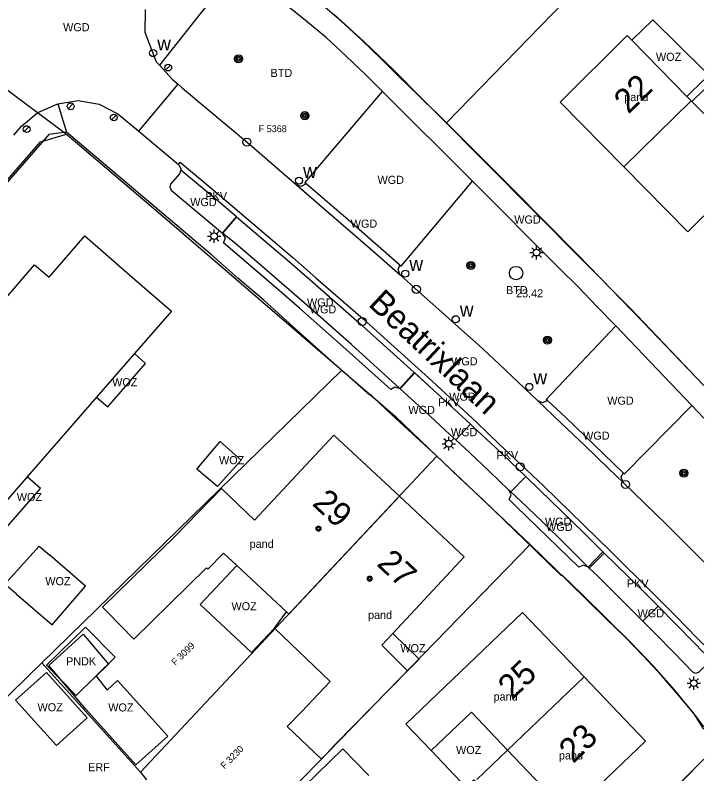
# Model space of a CAD drawing. Extents: x 198240 to 198429, y 356553 to 356721.
# Drawn here: x 198378.2 to 198429.3, y 356582.9 to 356639.1 of the extents above; entities that cross this region are included whole.
import ezdxf

# ---------------------------------------------------------------- set-up
doc = ezdxf.new("R2010")
doc.units = 0
for name, color, linetype in [('(presentatie) Code PNDK (symbool) (zonder attributen) niet in de presentatietabel', 7, 'Continuous'), ('Afsluitpaal', 7, 'Continuous'), ('begroeid terreindeel kenmerkpunt', 7, 'Continuous'), ('bijgebouw', 7, 'Continuous'), ('BOOM', 7, 'Continuous'), ('grens individueel parkeervak', 7, 'Continuous'), ('Grens maaiveld', 7, 'Continuous'), ('grens WOZ object', 7, 'Continuous'), ('hoofdgebouw', 7, 'Continuous'), ('Hoogtepunt', 7, 'Continuous'), ('huisnummerreeks BGT', 7, 'Continuous'), ('identificerend kenmerkpunt pand', 7, 'Continuous'), ('identificerend kenmerkpunt parkeervak', 7, 'Continuous'), ('identificerend kenmerkpunt WOZ object', 7, 'Continuous'), ('Inspectieput_rioolput', 7, 'Continuous'), ('kant verharding', 7, 'Continuous'), ('kolk', 7, 'Continuous'), ('LICHTMAST', 7, 'Continuous'), ('onbegroeid terreindeel kenmerkpunt', 7, 'Continuous'), ('openbare ruimte label tekst', 7, 'Continuous'), ('Perceelnummer', 7, 'Continuous'), ('perceelsgrens_definitief', 7, 'Continuous'), ('tussenmuur', 7, 'Continuous'), ('vlakafsluiter', 7, 'Continuous'), ('waterleidingput', 7, 'Continuous'), ('wegdeel kenmerkpunt', 7, 'Continuous'), ('weginrichtingselement lijn', 7, 'Continuous'), ('WOZ object als punt', 7, 'Continuous')]:
    doc.layers.add(name, color=color, linetype=linetype)

msp = doc.modelspace()

# ---------------------------------------------------------------- linework, layer by layer
at = {"layer": 'Afsluitpaal'}
for p, q in [((198389.752, 356635.373), (198389.402, 356635.016)), ((198382.523, 356632.501), (198382.173, 356632.144)), ((198385.717, 356631.672), (198385.367, 356631.315)), ((198379.266, 356630.817), (198378.916, 356630.46))]:
    msp.add_line(p, q, dxfattribs=at)
for centre in [(198389.579, 356635.193), (198382.35, 356632.321), (198385.544, 356631.492), (198379.093, 356630.637)]:
    msp.add_circle(centre, 0.25, dxfattribs=at)
at = {"layer": 'bijgebouw'}
msp.add_lwpolyline([(198404.433, 356582.738), (198402.513, 356584.711), (198393.844, 356576.278)], dxfattribs=at)
at = {"layer": 'BOOM'}
for centre, radius in [((198394.789, 356635.842), 0.3), ((198394.789, 356635.842), 0.2), ((198394.789, 356635.842), 0.1), ((198399.701, 356631.63), 0.3), ((198399.701, 356631.63), 0.2), ((198399.701, 356631.63), 0.1), ((198412, 356620.53), 0.3), ((198412, 356620.53), 0.2), ((198412, 356620.53), 0.1), ((198417.666, 356614.998), 0.3), ((198417.666, 356614.998), 0.2), ((198417.666, 356614.998), 0.1), ((198427.773, 356605.142), 0.3), ((198427.773, 356605.142), 0.2), ((198427.773, 356605.142), 0.1)]:
    msp.add_circle(centre, radius, dxfattribs=at)
at = {"layer": 'grens individueel parkeervak'}
for p, q in [((198393.611, 356622.929), (198394.644, 356624.13)), ((198406.736, 356611.407), (198407.804, 356612.596)), ((198407.804, 356612.596), (198408.885, 356611.623)), ((198408.885, 356611.623), (198411.957, 356608.785)), ((198411.957, 356608.785), (198410.875, 356607.614)), ((198416.055, 356604.889), (198414.957, 356603.76)), ((198420.762, 356598.101), (198421.877, 356599.222)), ((198425.862, 356595.279), (198424.743, 356594.175))]:
    msp.add_line(p, q, dxfattribs=at)
at = {"layer": 'Grens maaiveld'}
for p, q in [((198387.401, 356630.486), (198390.303, 356633.969)), ((198412.108, 356626.778), (198405.457, 356633.424)), ((198394.647, 356624.128), (198393.611, 356622.929)), ((198394.644, 356624.13), (198394.647, 356624.128)), ((198428.353, 356610.158), (198422.727, 356616.058)), ((198407.835, 356612.568), (198406.758, 356611.387)), ((198407.804, 356612.596), (198407.835, 356612.568)), ((198407.835, 356612.568), (198408.885, 356611.623)), ((198421.782, 356599.316), (198420.673, 356598.187)), ((198421.782, 356599.316), (198421.877, 356599.222))]:
    msp.add_line(p, q, dxfattribs=at)
for points in [[(198390.351, 356628.02), (198390.474, 356628.186), (198393.38, 356625.746), (198398.817, 356621.126), (198400.515, 356619.62), (198404.027, 356616.565), (198409.139, 356611.949), (198412.449, 356608.888), (198414.07, 356607.327), (198415.701, 356605.794), (198417.373, 356604.2), (198422.346, 356599.356), (198425.506, 356596.239), (198427.177, 356594.549), (198428.749, 356592.925), (198429.251, 356592.414)], [(198394.647, 356624.128), (198398.552, 356620.797), (198400.287, 356619.294), (198403.74, 356616.251), (198407.804, 356612.596)], [(198416.055, 356604.889), (198417.102, 356603.887), (198420.322, 356600.761), (198421.782, 356599.316)], [(198382.763, 356588.673), (198385.648, 356591.501), (198383.456, 356593.736), (198380.572, 356590.908), (198382.763, 356588.673)]]:
    msp.add_lwpolyline(points, dxfattribs=at)
at = {"layer": 'grens WOZ object'}
for p, q in [((198428.372, 356632.684), (198429.251, 356633.549)), ((198391.948, 356595.404), (198394.663, 356598.297)), ((198395.738, 356591.846), (198391.948, 356595.404)), ((198397.445, 356593.664), (198395.738, 356591.846)), ((198412.437, 356582.444), (198414.721, 356584.63))]:
    msp.add_line(p, q, dxfattribs=at)
for points in [[(198423.912, 356637.214), (198425.477, 356638.743), (198429.251, 356635.003)], [(198429.251, 356634.286), (198428.004, 356633.058)], [(198384.269, 356610.774), (198385.099, 356610.052), (198387.904, 356613.278), (198387.074, 356614)], [(198391.701, 356605.434), (198393.43, 356607.5), (198394.985, 356606.117), (198393.222, 356604.147), (198391.701, 356605.434)], [(198376.42, 356601.748), (198377.399, 356600.897), (198380.113, 356604.018), (198379.134, 356604.869)], [(198378.332, 356596.184), (198377.486, 356596.927), (198380.014, 356599.745), (198380.819, 356599.057)], [(198378.332, 356596.184), (198380.974, 356593.898), (198383.461, 356596.771), (198380.819, 356599.057)], [(198383.475, 356587.665), (198380.724, 356590.901), (198383.272, 356593.219), (198385.145, 356590.982), (198384.231, 356590.1), (198385.044, 356589.073)], [(198407.305, 356590.49), (198408.161, 356591.371), (198406.214, 356593.274)], [(198380.563, 356590.378), (198383.579, 356587.014), (198381.293, 356584.965), (198378.277, 356588.329), (198380.563, 356590.378)], [(198383.475, 356587.665), (198387.187, 356583.535), (198389.545, 356585.651), (198385.833, 356589.781), (198385.044, 356589.073)], [(198409.054, 356584.582), (198411.65, 356581.864), (198412.216, 356582.419), (198412.308, 356582.321)]]:
    msp.add_lwpolyline(points, dxfattribs=at)
at = {"layer": 'hoofdgebouw'}
for p, q in [((198423.912, 356637.214), (198428.004, 356633.058)), ((198428.004, 356633.058), (198428.318, 356632.739)), ((198428.372, 356632.684), (198428.318, 356632.739)), ((198428.372, 356632.684), (198429.251, 356631.791)), ((198387.106, 356619.502), (198389.812, 356617.148)), ((198389.812, 356617.148), (198387.074, 356614)), ((198387.074, 356614), (198384.269, 356610.774)), ((198384.269, 356610.774), (198379.134, 356604.869)), ((198379.134, 356604.869), (198376.42, 356601.748)), ((198393.684, 356599.212), (198394.663, 356598.297)), ((198394.663, 356598.297), (198398.338, 356594.861)), ((198385.074, 356594.841), (198387.025, 356592.851)), ((198397.445, 356593.664), (198398.338, 356594.861)), ((198405.392, 356592.395), (198406.214, 356593.274)), ((198407.305, 356590.49), (198405.392, 356592.395)), ((198401.981, 356585.072), (198407.305, 356590.49))]:
    msp.add_line(p, q, dxfattribs=at)
for points in [[(198423.328, 356627.83), (198418.602, 356632.63), (198423.566, 356637.565), (198423.912, 356637.214)], [(198423.328, 356627.83), (198428.055, 356623.028), (198429.251, 356624.217)], [(198360.274, 356583.182), (198357.56, 356580.061), (198351.153, 356585.634), (198353.818, 356588.702), (198352.758, 356589.611), (198356.269, 356593.637), (198357.324, 356592.737), (198361.192, 356597.186), (198360.148, 356598.119), (198363.635, 356602.123), (198364.703, 356601.223), (198369.86, 356607.147), (198368.781, 356608.057), (198372.281, 356612.093), (198373.369, 356611.185), (198377.239, 356615.604), (198376.168, 356616.531), (198379.668, 356620.576), (198380.75, 356619.653), (198383.405, 356622.721), (198387.106, 356619.502)], [(198406.698, 356603.432), (198401.85, 356607.965), (198395.961, 356601.666)], [(198395.961, 356601.666), (198393.536, 356604.004), (198390.102, 356600.479), (198384.72, 356595.202), (198385.074, 356594.841)], [(198406.214, 356593.274), (198411.508, 356598.935), (198406.698, 356603.432)], [(198387.025, 356592.851), (198392.407, 356598.128), (198392.518, 356598.036), (198393.684, 356599.212)], [(198420.379, 356590.045), (198415.818, 356594.814), (198407.174, 356586.548), (198409.054, 356584.582)], [(198399.458, 356587.46), (198401.569, 356589.712), (198397.445, 356593.664)], [(198414.721, 356584.63), (198419.264, 356579.863), (198424.933, 356585.283), (198420.379, 356590.045)], [(198401.981, 356585.072), (198400.944, 356583.951), (198398.386, 356586.376), (198399.458, 356587.46)], [(198414.721, 356584.63), (198412.038, 356587.436), (198409.054, 356584.582)]]:
    msp.add_lwpolyline(points, dxfattribs=at)
at = {"layer": 'Inspectieput_rioolput'}
msp.add_circle((198415.345, 356619.967), 0.5, dxfattribs=at)
at = {"layer": 'kant verharding'}
for p, q in [((198387.401, 356630.486), (198390.351, 356628.02)), ((198406.758, 356611.387), (198406.736, 356611.407)), ((198414.957, 356603.76), (198414.818, 356603.89)), ((198420.762, 356598.101), (198420.673, 356598.187))]:
    msp.add_line(p, q, dxfattribs=at)
for points in [[(198429.251, 356611.63), (198423.819, 356617.345), (198409.544, 356631.708), (198408.091, 356633.148), (198406.605, 356634.587), (198405.359, 356635.839), (198403.884, 356637.248), (198402.388, 356638.638), (198400.833, 356639.97), (198393.74, 356645.683)], [(198405.457, 356633.424), (198404.207, 356634.656), (198402.756, 356636.046), (198401.298, 356637.391), (198399.756, 356638.679), (198394.727, 356642.73), (198388.921, 356635.368)], [(198388.921, 356635.368), (198388.706, 356635.6), (198387.879, 356637.792), (198387.884, 356639.508)], [(198388.921, 356635.368), (198389.879, 356634.336), (198390.303, 356633.969)], [(198390.303, 356633.969), (198390.646, 356633.671), (198395.594, 356629.511), (198399.076, 356626.51)], [(198399.794, 356626.571), (198399.707, 356626.646), (198405.457, 356633.424)], [(198378.133, 356630.181), (198378.722, 356630.856), (198379.929, 356631.864), (198381.394, 356632.501)], [(198381.394, 356632.501), (198382.909, 356632.765), (198384.458, 356632.488), (198385.857, 356631.776), (198387.401, 356630.486)], [(198382.054, 356630.413), (198380.73, 356630.231), (198344.191, 356588.273)], [(198429.251, 356586.163), (198428.533, 356587.306), (198427.059, 356589.105), (198425.554, 356590.824), (198423.841, 356592.587), (198422.054, 356594.368), (198420.263, 356596.131), (198418.74, 356597.61), (198418.684, 356597.56), (198416.787, 356599.424), (198412.901, 356603.163), (198411.158, 356604.8), (198409.368, 356606.497), (198407.657, 356608.089), (198405.801, 356609.79), (198404.573, 356610.98), (198404.508, 356610.918), (198402.536, 356612.682), (198400.516, 356614.473), (198398.571, 356616.223), (198396.659, 356617.972), (198394.731, 356619.585), (198392.786, 356621.33), (198382.054, 356630.413)], [(198390.351, 356628.02), (198390.534, 356627.659), (198390.507, 356627.59)], [(198390.507, 356627.59), (198390.403, 356627.322), (198389.759, 356626.559), (198389.689, 356626.348), (198389.807, 356626.113), (198393.611, 356622.929)], [(198394.644, 356624.13), (198393.131, 356625.407), (198390.507, 356627.59)], [(198406.743, 356620.544), (198406.825, 356620.476), (198412.108, 356626.778)], [(198422.727, 356616.058), (198421.324, 356617.489), (198419.957, 356618.916), (198418.514, 356620.35), (198412.108, 356626.778)], [(198399.794, 356626.571), (198399.424, 356626.383), (198399.076, 356626.51)], [(198399.076, 356626.51), (198400.741, 356625.063), (198404.376, 356621.927), (198406.764, 356619.84)], [(198406.743, 356620.544), (198404.729, 356622.319), (198402.899, 356623.906), (198399.794, 356626.571)], [(198406.758, 356611.387), (198406.365, 356611.514), (198406.061, 356611.341), (198402.761, 356614.308), (198399.298, 356617.361), (198397.596, 356618.846), (198393.68, 356622.21), (198393.81, 356622.554), (198393.611, 356622.929)], [(198406.736, 356611.407), (198403.153, 356614.683), (198399.647, 356617.764), (198396.145, 356620.789), (198394.601, 356622.108), (198393.611, 356622.929)], [(198406.764, 356619.84), (198406.601, 356620.23), (198406.743, 356620.544)], [(198406.764, 356619.84), (198408.114, 356618.611), (198409.623, 356617.277), (198411.103, 356615.939), (198412.586, 356614.617), (198414.071, 356613.249), (198416.967, 356610.501)], [(198417.676, 356610.523), (198417.585, 356610.6), (198422.727, 356616.058)], [(198410.875, 356607.614), (198410.442, 356608.018), (198408.98, 356609.362), (198406.758, 356611.387)], [(198417.676, 356610.523), (198417.312, 356610.35), (198416.967, 356610.501)], [(198416.967, 356610.501), (198418.668, 356608.867), (198420.467, 356607.157), (198422.176, 356605.508), (198423.279, 356604.461)], [(198423.272, 356605.163), (198422.544, 356605.881), (198419.02, 356609.266), (198417.676, 356610.523)], [(198423.272, 356605.163), (198423.364, 356605.094), (198428.353, 356610.158)], [(198428.353, 356610.158), (198429.251, 356609.211)], [(198416.055, 356604.889), (198413.83, 356607.034), (198412.177, 356608.581), (198411.957, 356608.785)], [(198414.818, 356603.89), (198413.368, 356605.259), (198411.917, 356606.643), (198410.875, 356607.614)], [(198423.279, 356604.461), (198423.13, 356604.836), (198423.272, 356605.163)], [(198423.279, 356604.461), (198426.468, 356601.352), (198429.251, 356598.568)], [(198420.673, 356598.187), (198420.308, 356598.332), (198419.984, 356598.175), (198416.909, 356601.174), (198415.317, 356602.709), (198414.834, 356603.184), (198414.984, 356603.525), (198414.818, 356603.89)], [(198420.673, 356598.187), (198418.992, 356599.876), (198417.293, 356601.53), (198415.671, 356603.088), (198414.957, 356603.76)], [(198425.862, 356595.279), (198425.221, 356595.929), (198423.654, 356597.485), (198421.877, 356599.222)], [(198424.743, 356594.175), (198424.243, 356594.68), (198422.818, 356596.095), (198421.388, 356597.499), (198420.762, 356598.101)], [(198429.251, 356591.826), (198428.484, 356592.618), (198425.862, 356595.279)], [(198429.251, 356590.76), (198428.855, 356590.38), (198428.626, 356590.299), (198428.426, 356590.389), (198427.052, 356591.822), (198425.646, 356593.263), (198424.743, 356594.175)], [(198398.992, 356553.702), (198424.254, 356578.89), (198429.251, 356583.945)]]:
    msp.add_lwpolyline(points, dxfattribs=at)
at = {"layer": 'kolk'}
for centre in [(198395.405, 356629.673), (198407.955, 356618.764), (198403.943, 356616.375), (198415.642, 356605.618), (198423.454, 356604.309)]:
    msp.add_circle(centre, 0.3, dxfattribs=at)
at = {"layer": 'LICHTMAST'}
for p, q in [((198392.482, 356622.698), (198392.732, 356622.698)), ((198392.805, 356622.875), (198392.628, 356623.052)), ((198392.982, 356622.948), (198392.982, 356623.198)), ((198393.159, 356622.875), (198393.336, 356623.052)), ((198393.232, 356622.698), (198393.482, 356622.698)), ((198392.628, 356622.344), (198392.805, 356622.521)), ((198392.982, 356622.198), (198392.982, 356622.448)), ((198393.336, 356622.344), (198393.159, 356622.521)), ((198416.685, 356621.662), (198416.508, 356621.839)), ((198416.862, 356621.735), (198416.862, 356621.985)), ((198417.039, 356621.662), (198417.216, 356621.839)), ((198416.362, 356621.485), (198416.612, 356621.485)), ((198416.508, 356621.131), (198416.685, 356621.308)), ((198416.862, 356620.985), (198416.862, 356621.235)), ((198417.216, 356621.131), (198417.039, 356621.308)), ((198417.112, 356621.485), (198417.362, 356621.485)), ((198410.181, 356607.504), (198410.004, 356607.681)), ((198410.358, 356607.577), (198410.358, 356607.827)), ((198410.535, 356607.504), (198410.712, 356607.681)), ((198409.858, 356607.327), (198410.108, 356607.327)), ((198410.004, 356606.973), (198410.181, 356607.15)), ((198410.358, 356606.827), (198410.358, 356607.077)), ((198410.712, 356606.973), (198410.535, 356607.15)), ((198410.608, 356607.327), (198410.858, 356607.327)), ((198428.514, 356589.829), (198428.514, 356590.079)), ((198428.014, 356589.579), (198428.264, 356589.579)), ((198428.337, 356589.756), (198428.16, 356589.933)), ((198428.691, 356589.756), (198428.868, 356589.933)), ((198428.764, 356589.579), (198429.014, 356589.579)), ((198428.16, 356589.225), (198428.337, 356589.402)), ((198428.514, 356589.079), (198428.514, 356589.329)), ((198428.868, 356589.225), (198428.691, 356589.402))]:
    msp.add_line(p, q, dxfattribs=at)
for centre in [(198392.982, 356622.698), (198416.862, 356621.485), (198410.358, 356607.327), (198428.514, 356589.579)]:
    msp.add_circle(centre, 0.25, dxfattribs=at)
at = {"layer": 'perceelsgrens_definitief'}
for points in [[(198410.2, 356631.088), (198424.066, 356645.393)], [(198408.397, 356632.877), (198406.267, 356635.018), (198404.086, 356637.108), (198401.857, 356639.146)], [(198372.192, 356637.612), (198382.048, 356630.256)], [(198410.2, 356631.088), (198408.397, 356632.877)], [(198429.251, 356611.64), (198424.754, 356616.33), (198419.937, 356621.283), (198415.086, 356626.203), (198410.2, 356631.088)], [(198344.27, 356586.164), (198344.308, 356588.473), (198380.117, 356629.684), (198382.048, 356630.256)], [(198382.048, 356630.256), (198389.679, 356623.767), (198402.434, 356612.775)], [(198402.434, 356612.775), (198380.205, 356591.088)], [(198402.434, 356612.775), (198406.392, 356609.366), (198409.477, 356606.392)], [(198387.513, 356582.994), (198409.477, 356606.392)], [(198409.477, 356606.392), (198416.379, 356599.858)], [(198393.504, 356576.321), (198416.379, 356599.858)], [(198422.026, 356594.351), (198419.212, 356597.114), (198416.379, 356599.858)], [(198428.623, 356587.179), (198427.386, 356588.687), (198426.107, 356590.16), (198424.787, 356591.595), (198423.426, 356592.993), (198422.026, 356594.351)], [(198358.164, 356569.531), (198380.205, 356591.088)], [(198380.205, 356591.088), (198387.513, 356582.994)], [(198429.251, 356586.345), (198428.623, 356587.179)], [(198407.251, 356562.099), (198429.251, 356583.95)], [(198387.513, 356582.994), (198387.979, 356582.417)]]:
    msp.add_lwpolyline(points, dxfattribs=at)
at = {"layer": 'tussenmuur'}
for p, q in [((198428.318, 356632.739), (198423.328, 356627.83)), ((198420.379, 356590.045), (198414.721, 356584.63))]:
    msp.add_line(p, q, dxfattribs=at)
msp.add_lwpolyline([(198398.338, 356594.861), (198398.505, 356594.705), (198406.698, 356603.432)], dxfattribs=at)
at = {"layer": 'vlakafsluiter'}
msp.add_line((198381.394, 356632.501), (198382.054, 356630.413), dxfattribs=at)
at = {"layer": 'waterleidingput'}
for centre in [(198388.461, 356636.268), (198388.461, 356636.268), (198399.262, 356626.817), (198399.262, 356626.817), (198407.135, 356619.925), (198407.135, 356619.925), (198410.876, 356616.545), (198410.876, 356616.545), (198416.329, 356611.532), (198416.329, 356611.532)]:
    msp.add_circle(centre, 0.263, dxfattribs=at)
at = {"layer": 'weginrichtingselement lijn'}
msp.add_lwpolyline([(198390.351, 356628.02), (198390.474, 356628.186), (198393.38, 356625.746), (198398.817, 356621.126), (198400.515, 356619.62), (198404.027, 356616.565), (198409.139, 356611.949), (198412.449, 356608.888), (198414.07, 356607.327), (198415.701, 356605.794), (198417.373, 356604.2), (198422.346, 356599.356), (198425.506, 356596.239), (198427.177, 356594.549), (198428.749, 356592.925), (198429.251, 356592.414)], dxfattribs=at)
at = {"layer": 'WOZ object als punt'}
for centre, radius in [((198400.707, 356601.038), 0.178), ((198400.707, 356601.038), 0.178), ((198400.707, 356601.038), 0.178), ((198400.707, 356601.038), 0.178), ((198400.707, 356601.038), 0.1), ((198400.707, 356601.038), 0.1), ((198400.707, 356601.038), 0.1), ((198400.707, 356601.038), 0.1), ((198404.502, 356597.33), 0.178), ((198404.502, 356597.33), 0.178), ((198404.502, 356597.33), 0.178), ((198404.502, 356597.33), 0.178), ((198404.502, 356597.33), 0.1), ((198404.502, 356597.33), 0.1), ((198404.502, 356597.33), 0.1), ((198404.502, 356597.33), 0.1)]:
    msp.add_circle(centre, radius, dxfattribs=at)
for centre, start, end in [((198400.707, 356601.038), 0, 180), ((198400.707, 356601.038), 0, 180), ((198400.707, 356601.038), 0, 180), ((198400.707, 356601.038), 0, 180), ((198400.707, 356601.038), 0, 180), ((198400.707, 356601.038), 0, 180), ((198400.707, 356601.038), 0, 180), ((198400.707, 356601.038), 0, 180), ((198400.707, 356601.038), 180, 0), ((198400.707, 356601.038), 180, 0), ((198400.707, 356601.038), 180, 0), ((198400.707, 356601.038), 180, 0), ((198400.707, 356601.038), 180, 0), ((198400.707, 356601.038), 180, 0), ((198400.707, 356601.038), 180, 0), ((198400.707, 356601.038), 180, 0), ((198404.502, 356597.33), 0, 180), ((198404.502, 356597.33), 0, 180), ((198404.502, 356597.33), 0, 180), ((198404.502, 356597.33), 0, 180), ((198404.502, 356597.33), 0, 180), ((198404.502, 356597.33), 0, 180), ((198404.502, 356597.33), 0, 180), ((198404.502, 356597.33), 0, 180), ((198404.502, 356597.33), 180, 0), ((198404.502, 356597.33), 180, 0), ((198404.502, 356597.33), 180, 0), ((198404.502, 356597.33), 180, 0), ((198404.502, 356597.33), 180, 0), ((198404.502, 356597.33), 180, 0), ((198404.502, 356597.33), 180, 0), ((198404.502, 356597.33), 180, 0)]:
    msp.add_arc(centre, 0.178, start, end, dxfattribs=at)

# ---------------------------------------------------------------- texts
at = {"layer": '(presentatie) Code PNDK (symbool) (zonder attributen) niet in de presentatietabel'}
msp.add_text('PNDK', height=0.6, dxfattribs=at).set_placement((198382.009, 356590.905))
at = {"layer": 'begroeid terreindeel kenmerkpunt'}
for p in [(198397.157, 356634.497), (198414.601, 356618.405)]:
    msp.add_text('BTD', height=0.6, dxfattribs=at).set_placement(p)
at = {"layer": 'Hoogtepunt'}
msp.add_text('23.42', height=0.6, dxfattribs=at).set_placement((198415.345, 356618.167))
msp.add_text('23.42', height=0.6, dxfattribs=at).set_placement((198415.345, 356618.167))
at = {"layer": 'huisnummerreeks BGT'}
for s, rotation, p in [('22', 44.6, (198423.671, 356631.697)), ('29', 316.9, (198400.175, 356602.824)), ('27', 316.9, (198404.957, 356598.352)), ('25', 43.7, (198415.061, 356588.309)), ('23', 43.7, (198419.576, 356583.588))]:
    msp.add_text(s, height=1.8, rotation=rotation, dxfattribs=at).set_placement(p)
at = {"layer": 'identificerend kenmerkpunt pand'}
for p in [(198423.358, 356632.71), (198395.608, 356599.61), (198404.378, 356594.34), (198413.678, 356588.29), (198418.518, 356583.93)]:
    msp.add_text('pand', height=0.6, dxfattribs=at).set_placement(p)
at = {"layer": 'identificerend kenmerkpunt parkeervak'}
for p in [(198392.329, 356625.373), (198409.564, 356610.099), (198413.892, 356606.178), (198423.55, 356596.676)]:
    msp.add_text('PKV', height=0.6, dxfattribs=at).set_placement(p)
at = {"layer": 'identificerend kenmerkpunt WOZ object'}
for p in [(198425.705, 356635.689), (198385.423, 356611.584), (198393.339, 356605.809), (198378.36, 356603.077), (198380.474, 356596.842), (198394.263, 356594.984), (198406.772, 356591.88), (198379.896, 356587.497), (198385.135, 356587.487), (198410.897, 356584.332)]:
    msp.add_text('WOZ', height=0.6, dxfattribs=at).set_placement(p)
at = {"layer": 'onbegroeid terreindeel kenmerkpunt'}
msp.add_text('ERF', height=0.6, dxfattribs=at).set_placement((198383.646, 356583.053))
at = {"layer": 'openbare ruimte label tekst'}
msp.add_text('Beatrixlaan', height=1.8, rotation=316.9, dxfattribs=at).set_placement((198404.325, 356617.592))
at = {"layer": 'Perceelnummer'}
msp.add_text('F 5368', height=0.5, dxfattribs=at).set_placement((198396.277, 356630.41))
for s, rotation, p in [('F 3099', 44.4, (198390.104, 356590.853)), ('F 3230', 45.8, (198393.758, 356583.179))]:
    msp.add_text(s, height=0.5, rotation=rotation, dxfattribs=at).set_placement(p)
at = {"layer": 'waterleidingput'}
for p in [(198388.765, 356636.466), (198399.566, 356627.015), (198407.439, 356620.123), (198411.18, 356616.743), (198416.633, 356611.73)]:
    msp.add_text('w', height=1.05, dxfattribs=at).set_placement(p)
at = {"layer": 'wegdeel kenmerkpunt'}
for p in [(198381.79, 356637.886), (198405.081, 356626.575), (198391.207, 356624.928), (198403.097, 356623.33), (198415.208, 356623.634), (198399.858, 356617.494), (198400.062, 356616.982), (198410.532, 356613.132), (198410.391, 356610.511), (198422.096, 356610.214), (198407.368, 356609.531), (198410.515, 356607.879), (198420.31, 356607.622), (198417.482, 356601.248), (198417.571, 356600.859), (198424.347, 356594.462)]:
    msp.add_text('WGD', height=0.6, dxfattribs=at).set_placement(p)

doc.saveas('drawing.dxf')
